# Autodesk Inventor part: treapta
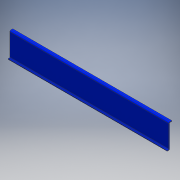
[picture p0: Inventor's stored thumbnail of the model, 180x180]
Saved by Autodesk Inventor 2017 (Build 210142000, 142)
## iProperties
Created: 2017-11
Part Number: treapta
Material: Generic
Document SubType Name: Sheet Metal
Designer: iusti
Density: 1 g/cm^3
Sheet Metal Rule: Default_mm
Appearance: Default
Author: iusti
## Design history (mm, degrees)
node "Contour Flange1"
  sketch "Sketch1"
    geometry: L1 (20.807, 182.422)-(0.807, 182.422); L2 (0.807, 182.422)-(0.807, -17.578); L3 (0.807, -17.578)-(-19.193, -17.578); 1 further point
    constraints: 6 end point, 2 perpendicular, 1 horizontal
    dimensions: "d0" = 20 distance of L1.start L1.end; "d1" = 20 distance of L2.end L3.end; "d2" = 200 distance of L1.end L2.end
body "Solid1"
face "Plate1" dims "d3" = 5 (= BendReliefWidth), "d4" = 2.5 (= BendReliefDepth), "d5" = 10 (= MinimumRemnant), "d6" = 5 (= BendRadius), "d7" = 1350, "d8" = 5 (= BendRadius), "d9" = 0.5, "d10" = 20 (= CornerReliefSize), "d11" = 5 (= GapSize), "d12" = 5 (= JacobiRadiusSize), "SeamGap" = 0.01, "Thickness" = 5 (derived)
bend "Bend1" dims "d3" = 5 (= BendReliefWidth), "d4" = 2.5 (= BendReliefDepth), "d5" = 10 (= MinimumRemnant), "d6" = 5 (= BendRadius), "d8" = 5 (= BendRadius), "d9" = 0.5, "SeamGap" = 0.01, "Thickness" = 5 (derived)
feature "Corner1" dims "d9" = 0.5, "d10" = 20 (= CornerReliefSize), "d11" = 5 (= GapSize), "d12" = 5 (= JacobiRadiusSize)
other parameters: "BendRadius" = 5 (= Thickness), "BendReliefWidth" = 5 (= Thickness), "BendReliefDepth" = 2.5 (= 0.5 x Thickness), "TransitionRadius" = 5 (= BendRadius), "JacobiRadiusSize" = 5 (= BendRadius), "GapSize" = 5 (= Thickness)
